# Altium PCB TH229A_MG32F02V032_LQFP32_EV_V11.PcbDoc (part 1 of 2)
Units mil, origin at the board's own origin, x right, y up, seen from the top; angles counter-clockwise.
Board outline 4094.49 x 2637.8 mil, 2 copper layers (Top Layer, Bottom Layer); 124 components, 101 nets, 554 pads, 263 vias.
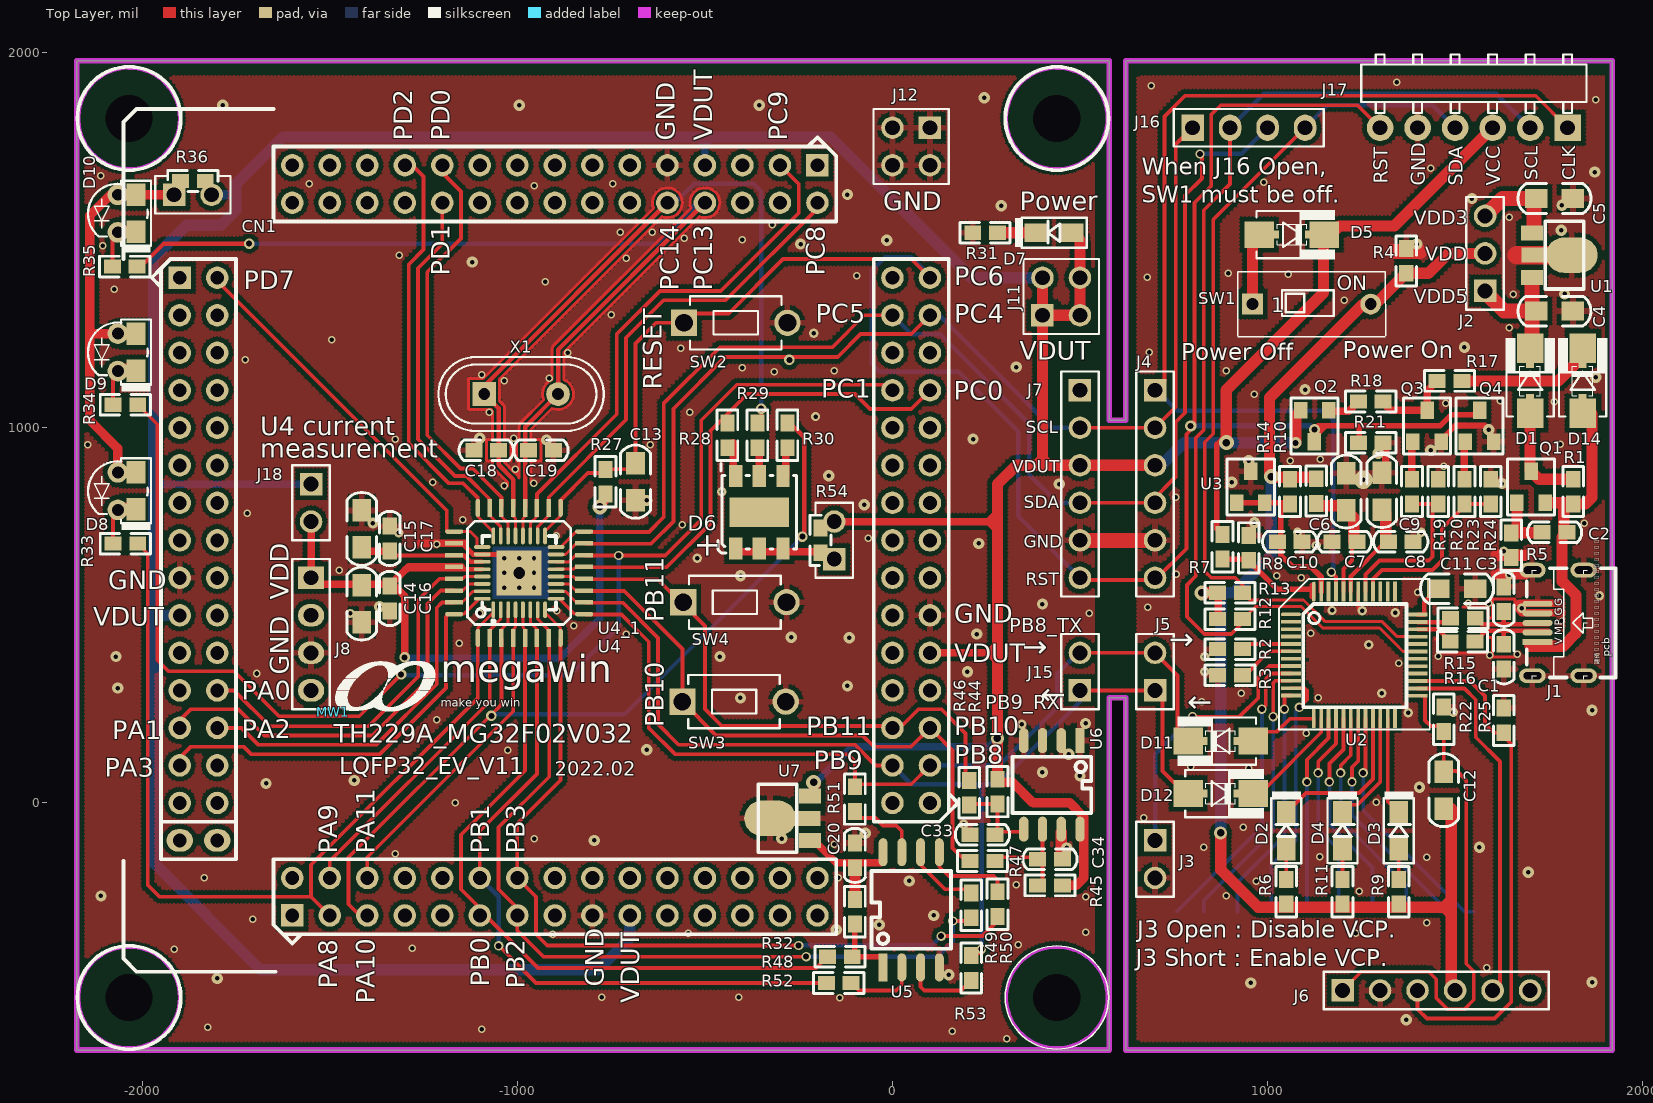
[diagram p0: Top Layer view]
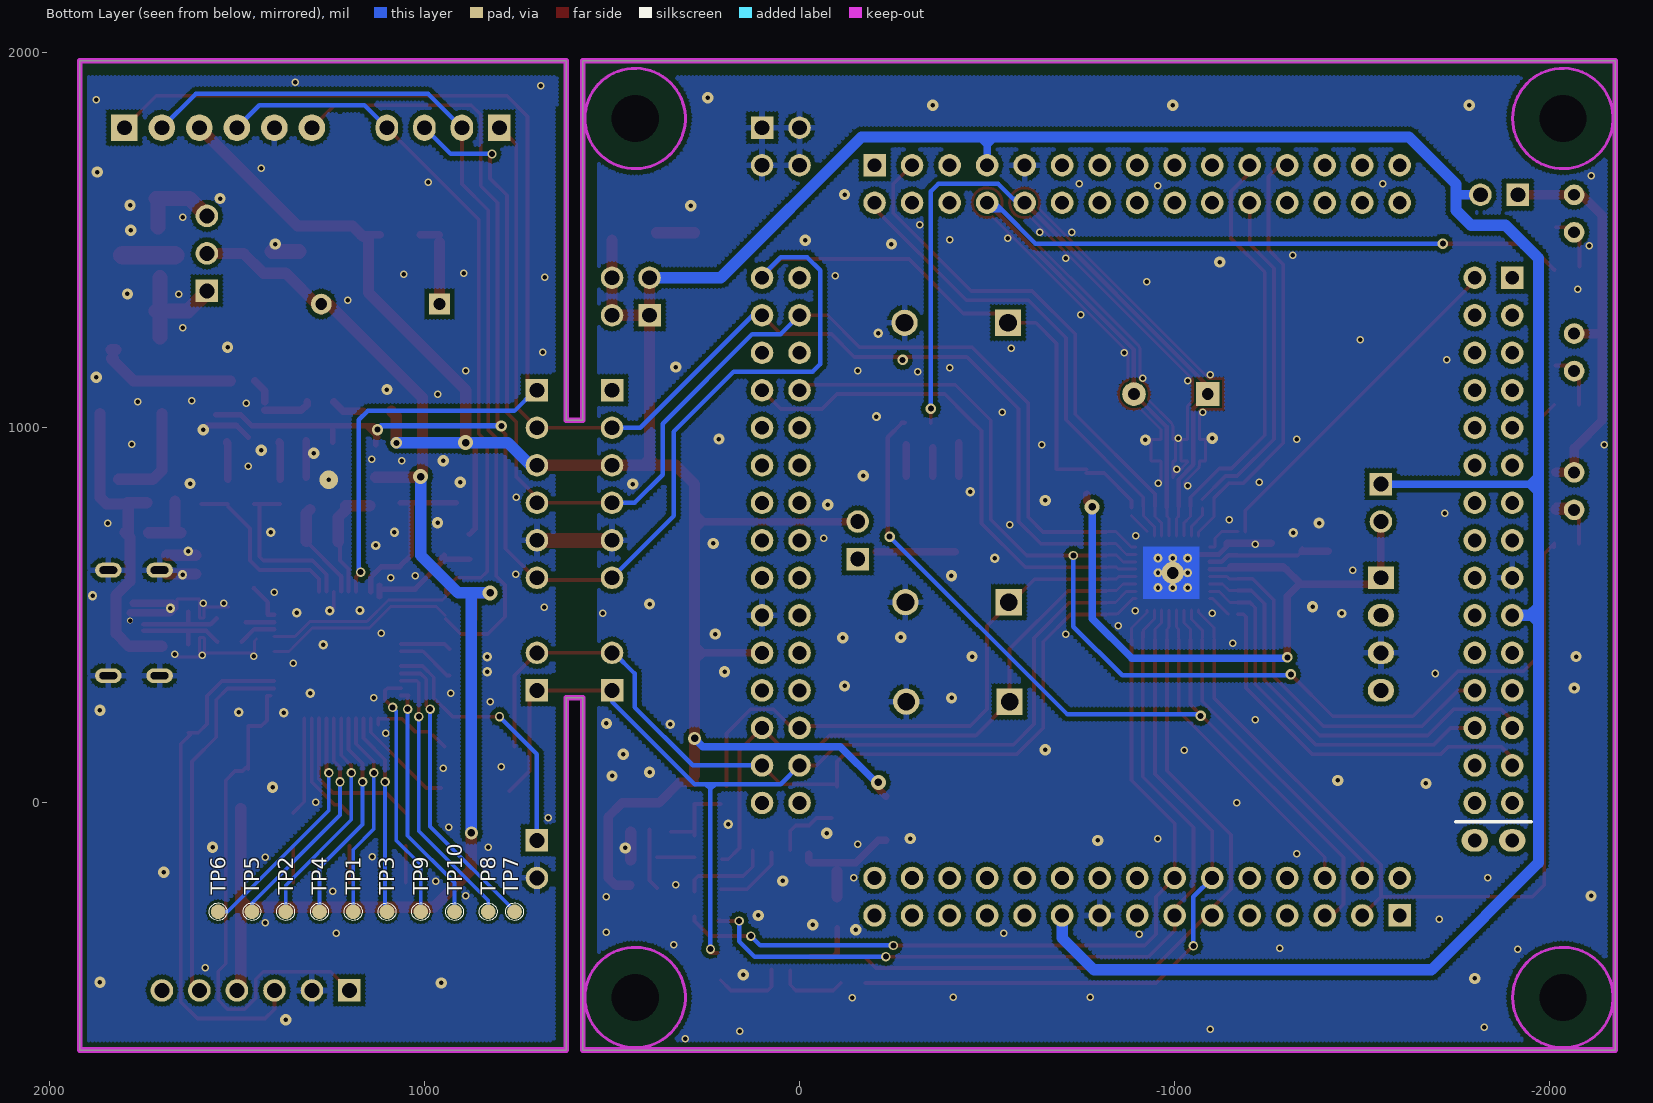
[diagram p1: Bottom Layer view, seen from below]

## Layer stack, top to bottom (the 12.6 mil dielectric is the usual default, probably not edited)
Top Layer: signal copper 1.4
Dielectric: dielectric 12.6, FR-4, Dk 4.8
Bottom Layer: signal copper 1.4

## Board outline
-2175.04,-658.74 -2175.04,1979.06 578.35,1979.06 578.35,1020 621.65,1020 621.65,1979.06 1919.45,1979.06 1919.45,-658.74 621.65,-658.74 621.65,280 578.35,280 578.35,-658.74

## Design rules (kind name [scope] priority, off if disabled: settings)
Clearance 12 [All] p1: gap=12
Clearance 7 [All] p2 off: gap=7
Clearance 6 [All] p3: gap=6
HoleSize 500-HoleSize [All] p1: absolutevalues=TRUE maxlimit=1500 minlimit=1 maxpercent=80.000 minpercent=20.000
PolygonConnect VIA [ISVIA] p1: connectstyle=Direct reliefconductorwidth=10 reliefentries=4 polygonreliefangle="90 Angle"
PolygonConnect "15 PolygonConnect" [All] p2: connectstyle=Relief reliefconductorwidth=15 reliefentries=4 polygonreliefangle="90 Angle"
RoomDefinition 2_MG32F02V032_V11 [InComponentClass('2_MG32F02V032_V11')] p1: confinementstyle=ConfineIn formatcopy=TRUE lockcomponents=FALSE outline -2365.04,-833.74 2065,-833.74 2065,2051.26 -2365.04,2051.26
RoomDefinition 1_MLink_V11 [InComponentClass('1_MLink_V11')] p2: confinementstyle=ConfineIn formatcopy=TRUE lockcomponents=FALSE outline -2285.04,-878.74 2004.96,-878.74 2004.96,2116.26 -2285.04,2116.26
RoutingVias [All] p1: holewidth=16 width=28 viastyle="Through Hole" minholewidth=16 minwidth=25 maxholewidth=28 maxwidth=50
ShortCircuit [All] p1 off: allowed=FALSE
SilkscreenOverComponentPads [All] p1: minsilkscreentomaskgap=10
SolderMaskExpansion [All] p1: expansion=4
UnRoutedNet [All] p1 off:
Width [All] p1: maxlimit=100 minlimit=6 preferedwidth=10
24 further rules are at their usual default settings.

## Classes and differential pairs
component class 2_MG32F02V032_V11: C13 C14 C15 C16 C17 C18 C19 C20 C33 C34 CN1 D6 D7 D8 D9 D10 J7 J8 J11 J12 J15 J18 R27 R28 R29 R30 R31 R32 R33 R34 R35 R36 R44 R45 R46 R47 R48 R49 R50 R51 R52 R53 R54 SW2 SW3 SW4 U4 U4_1 U5 U6 U7 X1
component class 1_MLink_V11: C1 C2 C3 C4 C5 C6 C7 C8 C9 C10 C11 C12 D1 D2 D3 D4 D5 D11 D12 D14 J1 J2 J3 J4 J5 J6 J16 J17 MW1 Q1 Q2 Q3 Q4 R1 R2 R3 R4 R5 R6 R7 R8 R9 R10 R11 R12 R13 R14 R15 R16 R17 R18 R19 R20 R21 R22 R23 R24 R25 SW1 TP1 TP2 TP3 TP4 TP5 TP6 TP7 TP8 TP9 TP10 U1 U2 U3

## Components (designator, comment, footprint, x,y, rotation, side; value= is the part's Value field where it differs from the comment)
C1 "15pF" 0603C 1630,390 r90 top
C2 "0.1uF" 0603C 1764.96,721.26 r0 top
C3 "15pF" 0603C 1630,543 r270 top
C4 "4.7uF" 0805C 1764.96,1311.26 r0 top
C5 "4.7uF" 0805C 1764.96,1611.26 r0 top
C6 "4.7uF" 0805C 1209.96,830 r90 top
C7 "0.1uF" 0603C 1205,696.26 r180 top
C8 "0.1uF" 0603C 1355,696.26 r0 top
C9 "4.7uF" 0805C 1304.96,831.26 r90 top
C10 "0.1uF" 0603C 1059.05,696.26 r180 top
C11 "4.7uF" 0805C 1504.96,571.26 r0 top
C12 "4.7uF" 0805C 1470,34 r90 top
C13 "4.7uF" 0805C -685.04,856.26 r90 top
C14 "4.7uF" 0805C -1415.04,531.26 r270 top
C15 "4.7uF" 0805C -1415.04,730.47 r90 top
C16 "0.1uF" 0603C -1340.1,545 r90 top
C17 "0.1uF" 0603C -1340.04,705 r270 top
C18 "NC" 0603C -1083,940 r0 top
C19 "NC" 0603C -937,940 r180 top
C20 "1uF" 0603C -100,-140 r270 top
C33 "47pF" 0603C 240,-85 r0 top
C34 "47pF" 0603C 420,-150 r180 top
CN1 "QFP122-CKT" QFP122-P2.54-CKT -900,700 r0 top locked
D1 "1N5817" DIODE_SMA_SOD323 1699.96,1125 r90 top
D2 "Yellow" 0805D 1050,-73.74 r90 top
D3 "Green" 0805D 1350,-73.74 r90 top
D4 "Red" 0805D 1200,-73.74 r90 top
D5 "1N5817" DIODE_SMA_SOD323 1064.96,1515 r0 top
D6 "GTG5050RGBC" LED6P_RGB_SMD_50X50 -355,775 r90 top
D7 "Yellow" 0805D 430.79,1520 r180 top
D8 "Red" LED38+0805 -2065.04,831.26 r270 top
D9 "Yellow" LED38+0805 -2065.04,1201.26 r270 top
D10 "Green" LED38+0805 -2065.04,1571.26 r270 top
D11 "1N5817" DIODE_SMA_SOD323 875,165 r180 top
D12 "1N5817" DIODE_SMA_SOD323 875,25 r0 top
D14 "1N5817" DIODE_SMA_SOD323 1839.96,1125 r90 top
J1 "MICRO_USB" USB_MICRO_7.X6P065 1842.76,479.85 r90 top
J2 "2&3 (0 ohm)" PS3P254 1580,1365 r90 top
J3 "VCP Option" PS2P254 700,-100 r270 top
J4 "OnBoard ICP/SWD Connector" PS6P254 700,1100 r270 top
J5 "NC" PS2P254 700,300 r90 top
J6 "CON6" PS6P254 1200,-500 r0 top
J7 "CON6" PS6P254 500,1100 r270 top
J8 "1&2 (0 ohm)" PS4P254 -1550,600 r270 top
J11 "CONN SOCKET 2x2/SM" PS2X2P254 400,1300 r0 top
J12 "CONN SOCKET 2x2/SM" PS2X2P254 100,1800 r180 top
J15 "NC" PS2P254 500,300 r90 top
J16 "When J16 Open, SW1 must be off." PS4P254 800,1800 r0 top
J17 "Off Board ICP/SWD Connector" PS6P254_90 1800,1800 r180 top locked
J18 "JUMPER" PS2P254 -1550,850 r270 top
MW1 "MW-A4" MEGAWIN_3.4 -1490.72,242.24 r0 top
Q1 "IRLML6402" SOT23 1702.5,841.97 r0 top
Q2 "2N3906" SOT23 1125.46,1005 r180 top
Q3 "3904" SOT23_132 1425,1005 r0 top
Q4 "3904" SOT23_132 1565,1005 r0 top
R1 "NC" 0603R#1 1815,830 r270 top
R2 "0" 0603R#1 900,410 r0 top
R3 "NC" 0603R#1 900,340 r0 top
R4 "3.3K" 0603R#1 1370,1445 r270 top
R5 "1M" 0603R#1 1650,687 r270 top
R6 "1K" 0603R#1 1050,-236.74 r270 top
R7 "30K" 0603R#1 880,683 r90 top
R8 "10K" 0603R#1 950,680 r270 top
R9 "1K" 0603R#1 1350,-236.74 r270 top
R10 "10" 0603R#1 1129.96,831.26 r90 top
R11 "1K" 0603R#1 1200,-236.74 r270 top
R12 "1.5K" 0603R#1 900,490 r180 top
R13 "1.5K" 0603R#1 900,560 r180 top
R14 "1K" 0603R#1 1059.96,830 r270 top
R15 "30" 0603R#1 1520.84,492.31 r180 top
R16 "30" 0603R#1 1520,430 r180 top
R17 "4.7K" 0603R#1 1484.96,1125 r0 top
R18 "1K" 0603R#1 1275,1070 r0 top
R19 "4.7K" 0603R#1 1385,830 r270 top
R20 "10K" 0603R#1 1455,830 r270 top
R21 "1M" 0603R#1 1275,960 r180 top
R22 "47K" 0603R#1 1470,223 r90 top
R23 "4.7K" 0603R#1 1525,830 r270 top
R24 "10K" 0603R#1 1595,830 r270 top
R25 "47K" 0603R#1 1630,220 r270 top
R27 "47K" 0603R#1 -765.04,856.26 r270 top
R28 "510" 0603R#1 -440,980 r90 top
R29 "510" 0603R#1 -360,980 r90 top
R30 "3K" 0603R#1 -280,980 r90 top
R31 "1K" 0603R#1 247,1520 r180 top
R32 "47K" 0603R#1 -100,-290 r270 top
R33 "510" 0603R#1 -2045.04,691.26 r0 top
R34 "510" 0603R#1 -2045.04,1061.26 r0 top
R35 "510" 0603R#1 -2046.48,1429.81 r0 top
R36 "0" PS2p254+0603 -1915.04,1621.26 r0 top
R44 "10K" 0603R#1 280,30 r90 top
R45 "10K" 0603R#1 420,-220 r0 top
R46 "NC" 0603R#2 204.96,27 r270 top
R47 "NC" 0603R#1 240,-155 r180 top
R48 "NC" 0603R#1 -140,-410 r180 top
R49 "NC" 0603R#1 210,-273 r270 top
R50 "NC" 0603R#1 280,-270 r270 top
R51 "NC" 0603R#1 -100,10 r90 top
R52 "NC" 0603R#1 -143,-480 r180 top
R53 "NC" 0603R#1 210,-440 r90 top
R54 "0" PS2p254+0603 -155.04,650 r90 top
SW1 "SW KEY-SPST" DIP2_SW 960.04,1330 r0 top
SW2 "SW TACT-SPST" SW_T_2P -417.8,1280 r0 top
SW3 "SW TACT-SPST" SW_T_2P -422.21,270 r0 top
SW4 "SW TACT-SPST" SW_T_2P -420,535 r0 top
TP1 "T POINT A" PIN1_1H0 1190,-290 r90 bottom
TP2 "T POINT A" PIN1_1H0 1370,-290 r90 bottom
TP3 "T POINT A" PIN1_1H0 1100,-290 r180 bottom
TP4 "T POINT A" PIN1_1H0 1280,-290 r180 bottom
TP5 "T POINT A" PIN1_1H0 1460,-290 r180 bottom
TP6 "T POINT A" PIN1_1H0 1550,-290 r180 bottom
TP7 "T POINT A" PIN1_1H0 760,-290 r180 bottom
TP8 "T POINT A" PIN1_1H0 830,-290 r180 bottom
TP9 "T POINT A" PIN1_1H0 1010,-290 r180 bottom
TP10 "T POINT A" PIN1_1H0 920,-290 r90 bottom
U1 "AIC1734-33(SOT-89)" SOT89 1704.96,1460.31 r270 top
U2 "MG84FG516_LQFP48" LQFP48_7X7_050 1231.47,394.39 r270 top locked
U3 "TL431A" SOT23 954.96,841.97 r0 top
U4 "MG32F02A_LQFP48" QFP32-P0.8-Z8.8X8.8 -995.04,613.32 r90 top locked
U4_1 "MG32F02A__QFN32" QFN32-P0.5-Z5X5-TPAD -995.04,613.32 r90 top locked
U5 "MX25LXX-SOP" SO8_208P127 50,-285 r0 top
U6 "24C16-SOP" SO8_150P127 500,166.22 r270 top
U7 "AIC1734-33(SOT-89)" SOT89 -220,-40.94 r90 top
X1 "NC" X49U -990,1090 r0 top locked

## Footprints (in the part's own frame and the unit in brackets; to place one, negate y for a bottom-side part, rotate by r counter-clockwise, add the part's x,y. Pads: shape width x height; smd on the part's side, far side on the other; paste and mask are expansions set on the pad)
0603C [mil]
  rect 45x38 smd: 1(33,0) 2(-33,0)
  silkscreen extent -72,-28 72,28
0603R#1 [mil]
  rect 45x38 smd: 1(33,0) 2(-33,0)
  silkscreen extent -67,-28 67,28
0603R#2 [mil]
  rect 45x38 smd: 1(-33,0) 2(33,0)
  silkscreen extent -67,-28 67,28
0805C [mil]
  rect 60x50 smd: 1(-49.21,0) 2(49.21,0)
  silkscreen extent -97,-39 97,39
0805D [mil]
  rect 60x50 smd: 1(-49.21,0) 2(49.21,0)
  silkscreen extent -87,-40 104,40
DIODE_SMA_SOD323 [mm]
  rect 2x1.8 smd: 1(-2.2,0) 2(2.2,0)
  rect 0.95x0.54 smd: 1(-1.35,0) 2(1.35,0)
  silkscreen extent -2.4,-1.68 2.92,1.68
DIP2_SW [mm]
  rect 1.4x1.4 hole 0.8: 1(0,0)
  round 1.4 hole 0.8: 2(8,0)
  silkscreen extent -1.02,-2.2 9.02,2.2
LED6P_RGB_SMD_50X50 [mm]
  rect 2x4 smd: 0(0,0)
  rect 1.5x0.9 smd: 1(-2.45,1.6) 2(2.45,1.6) 3(-2.45,0) 4(2.45,0) 5(-2.45,-1.6) 6(2.45,-1.6)
  silkscreen extent -2.76,-2.52 3.3,2.79
LED38+0805 [mm]
  round 1.4 hole 0.8: 1(-1.27,0) 2(1.27,0)
  rect 1.524x1.27 smd: 1(-1.267,1.237) 2(1.233,1.237)
  silkscreen extent -2.23,-2.02 2.64,2.25
LQFP48_7X7_050 [mm]
  oval 0.254x1.35 smd: 1(-2.75,-4.292)
  rect 0.254x1.35 smd: 2(-2.25,-4.292) 3(-1.75,-4.292) 4(-1.25,-4.292) 5(-0.75,-4.292) 6(-0.25,-4.292) 7(0.25,-4.292) 8(0.75,-4.292) 9(1.25,-4.292) 10(1.75,-4.292) 11(2.25,-4.292) 12(2.75,-4.292) 25(2.763,4.292) 26(2.263,4.292) 27(1.763,4.292) 28(1.263,4.292) 29(0.763,4.292) 30(0.263,4.292) 31(-0.237,4.292) 32(-0.737,4.292) 33(-1.237,4.292) 34(-1.737,4.292) 35(-2.237,4.292) 36(-2.737,4.292)
  rect 1.35x0.254 smd: 13(4.286,-2.744) 14(4.286,-2.244) 15(4.286,-1.744) 16(4.286,-1.244) 17(4.286,-0.744) 18(4.286,-0.244) 19(4.286,0.256) 20(4.286,0.756) 21(4.286,1.256) 22(4.286,1.756) 23(4.286,2.256) 24(4.286,2.756) 37(-4.286,2.756) 38(-4.286,2.256) 39(-4.286,1.756) 40(-4.286,1.256) 41(-4.286,0.756) 42(-4.286,0.256) 43(-4.286,-0.244) 44(-4.286,-0.744) 45(-4.286,-1.244) 46(-4.286,-1.744) 47(-4.286,-2.244)
  oval 1.35x0.254 smd: 48(-4.286,-2.744)
  silkscreen extent -5.15,-5.09 5.05,5.11
MEGAWIN_3.4 [mil]
  silkscreen extent 5,3 272,136
PIN1_1H0 [mm]
  round 1 smd: 1(0,0)
  silkscreen extent -0.6,-0.6 0.6,0.6
PS2P254 [mil]
  rect 60x60 hole 39.37: 1(0,0)
  round 60 hole 39.37: 2(100,0)
  silkscreen extent -50,-50 150,50
PS2p254+0603 [mil]
  rect 60x60 hole 39.37: 1(0,0)
  rect 45x38 smd: 1(17,36.85) 2(83,36.85)
  round 60 hole 39.37: 2(100,0)
  silkscreen extent -50,-50 150,64
PS2X2P254 [mil]
  rect 60x60 hole 39.37: 1(0,0)
  round 60 hole 39.37: 2(0,100) 3(100,0) 4(100,100)
  silkscreen extent -50,-50 150,150
PS3P254 [mil]
  rect 60x60 hole 39.37: 1(0,0)
  round 60 hole 39.37: 2(100,0) 3(200,0)
  silkscreen extent -50,-50 250,50
PS4P254 [mil]
  rect 60x70 hole 39.37: 1(0,0)
  oval 60x70 hole 39.37: 2(100,0) 3(200,0) 4(300,0)
  silkscreen extent -50,-50 350,50
PS6P254 [mil]
  rect 60x60 hole 39.37: 1(0,0)
  round 60 hole 39.37: 2(100,0) 3(200,0) 4(300,0) 5(400,0) 6(500,0)
  silkscreen extent -50,-50 550,50
PS6P254_90 [mm]
  rect 1.8x1.8 hole 1: 1(0,0)
  round 1.8 hole 1: 2(2.54,0) 3(5.08,0) 4(7.62,0) 5(10.16,0) 6(12.7,0)
  silkscreen extent -1.27,-4.95 13.97,-1
QFN32-P0.5-Z5X5-TPAD [mm]
  oval 1.143x0.254 smd: 1(-2.5,1.75) 2(-2.5,1.25) 3(-2.5,0.75) 4(-2.5,0.25) 5(-2.5,-0.25) 6(-2.5,-0.75) 7(-2.5,-1.25) 8(-2.5,-1.75) 17(2.5,-1.75) 18(2.5,-1.25) 19(2.5,-0.75) 20(2.5,-0.25) 21(2.5,0.25) 22(2.5,0.75) 23(2.5,1.25) 24(2.5,1.75)
  oval 0.254x1.143 smd: 9(-1.75,-2.5) 10(-1.25,-2.5) 11(-0.75,-2.5) 12(-0.25,-2.5) 13(0.25,-2.5) 14(0.75,-2.5) 15(1.25,-2.5) 16(1.75,-2.5) 25(1.75,2.5) 26(1.25,2.5) 27(0.75,2.5) 28(0.25,2.5) 29(-0.25,2.5) 30(-0.75,2.5) 31(-1.25,2.5) 32(-1.75,2.5)
  rect 3.048x3.048 smd: 33(0,0)
  round 1.5 hole 0.8: 34(0,0)
  round 0.6 hole 0.3: 35(0,1) 36(1,1) 37(1,0) 38(1,-1) 39(0,-1) 40(-1,-1) 41(-1,0) 42(-1,1)
  silkscreen extent -3.35,-2.5 2.5,2.5
QFP32-P0.8-Z8.8X8.8 [mil]
  oval 48x12 smd: 1(-173.23,110.24) 8(-173.23,-110.24) 17(173.23,-110.24) 24(173.23,110.24)
  rect 48x12 smd: 2(-173.23,78.74) 3(-173.23,47.24) 4(-173.23,15.75) 5(-173.23,-15.75) 6(-173.23,-47.24) 7(-173.23,-78.74) 18(173.23,-78.74) 19(173.23,-47.24) 20(173.23,-15.75) 21(173.23,15.75) 22(173.23,47.24) 23(173.23,78.74)
  oval 12x48 smd: 9(-110.24,-173.23) 16(110.24,-173.23) 25(110.24,173.23) 32(-110.24,173.23)
  rect 12x48 smd: 10(-78.74,-173.23) 11(-47.24,-173.23) 12(-15.75,-173.23) 13(15.75,-173.23) 14(47.24,-173.23) 15(78.74,-173.23) 26(78.74,173.23) 27(47.24,173.23) 28(15.75,173.23) 29(-15.75,173.23) 30(-47.24,173.23) 31(-78.74,173.23)
  silkscreen extent -138,-138 138,138
QFP122-P2.54-CKT [mil]
  rect 60x60 hole 37: 1(-700,-1000) 61(700,1000) 91(-1000,700)
  round 60 hole 37: 2(-700,-900) 3(-600,-1000) 4(-600,-900) 5(-500,-1000) 6(-500,-900) 7(-400,-1000) 8(-400,-900) 9(-300,-1000) 10(-300,-900) 11(-200,-1000) 12(-200,-900) 13(-100,-1000) 14(-100,-900) 15(0,-1000) 16(0,-900) 17(100,-1000) 18(100,-900) 19(200,-1000) 20(200,-900) 21(300,-1000) 22(300,-900) 23(400,-1000) 24(400,-900) 25(500,-1000) 26(500,-900) 27(600,-1000) 28(600,-900) 29(700,-1000) 30(700,-900) 31(1000,-700) 32(900,-700) 33(1000,-600) 34(900,-600) 35(1000,-500) 36(900,-500) 37(1000,-400) 38(900,-400) 39(1000,-300) 40(900,-300) 41(1000,-200) 42(900,-200) 43(1000,-100) 44(900,-100) 45(1000,0) 46(900,0) 47(1000,100) 48(900,100) 49(1000,200) 50(900,200) 51(1000,300) 52(900,300) 53(1000,400) 54(900,400) 55(1000,500) 56(900,500) 57(1000,600) 58(900,600) 59(1000,700) 60(900,700) 62(700,900) 63(600,1000) 64(600,900) 65(500,1000) 66(500,900) 67(400,1000) 68(400,900) 69(300,1000) 70(300,900) 71(200,1000) 72(200,900) 73(100,1000) 74(100,900) 75(0,1000) 76(0,900) 77(-100,1000) 78(-100,900) 79(-200,1000) 80(-200,900) 81(-300,1000) 82(-300,900) 83(-400,1000) 84(-400,900) 85(-500,1000) 86(-500,900) 87(-600,1000) 88(-600,900) 89(-700,1000) 90(-700,900) 92(-900,700) 93(-1000,600) 94(-900,600) 95(-1000,500) 96(-900,500) 97(-1000,400) 98(-900,400) 99(-1000,300) 100(-900,300) 101(-1000,200) 102(-900,200) 103(-1000,100) 104(-900,100) 105(-1000,0) 106(-900,0) 107(-1000,-100) 108(-900,-100) 109(-1000,-200) 110(-900,-200) 111(-1000,-300) 112(-900,-300) 113(-1000,-400) 114(-900,-400) 115(-1000,-500) 116(-900,-500) 117(-1000,-600) 118(-900,-600) 119(-1000,-700) 120(-900,-700)
  oval 70x60 hole 37: 121(-1000,-800) 122(-900,-800)
  silkscreen extent -1150,-1150 1075,1150
SO8_150P127 [mil]
  rect 67x25 smd: 1(0,0)
  oval 67x25 smd: 2(0,-50) 3(0,-100) 4(0,-150) 5(236.22,-150) 6(236.22,-100) 7(236.22,-50) 8(236.22,0)
  silkscreen extent 43,-180 193,30
SO8_208P127 [mm]
  rect 0.6x1.9 smd: 1(-1.905,-3.9)
  oval 0.6x1.9 smd: 2(-0.635,-3.9) 3(0.635,-3.9) 4(1.905,-3.9) 5(1.905,3.9) 6(0.635,3.9) 7(-0.635,3.9) 8(-1.905,3.9)
  silkscreen extent -2.69,-2.63 2.69,2.63
SOT23 [mil]
  rect 36x43.31 smd: 1(-37.5,-41.97) 2(37.5,-41.97)
  rect 36x46.06 smd: 3(0.5,41.97)
  silkscreen extent -63,-74 63,75
SOT23_132 [mil]
  rect 36x43.31 smd: 1(-37.5,-41.97) 3(37.5,-41.97)
  rect 36x46.06 smd: 2(0.5,41.97)
  silkscreen extent -63,-74 63,75
SOT89 [mm]
  rect 1.016x1.5 smd: 1(-1.5,0) 3(1.5,0)
  oval 2.4x3.5 smd: 2(0,2.7)
  rect 1.016x2.6 smd: 2(0,0.6)
  silkscreen extent -2.3,0.9 2.3,3.5
SW_T_2P [mil]
  rect 70x70 hole 47.24: 1(-137.79,0)
  round 70 hole 47.24: 2(137.8,0)
  silkscreen extent -122,-71 122,71
USB_MICRO_7.X6P065 [mm] "J?"
  rect 0.4x2.032 smd: 1(-1.3,3.119)
  oval 0.4x2.032 smd: 2(-0.65,3.119) 3(0,3.119) 4(0.65,3.119) 5(1.3,3.119)
  oval 1x1.8 hole 0.5 slot 1.2 at 90 deg: 6(3.575,3.47) 7(3.575,0) 8(-3.575,0) 9(-3.575,3.47)
  silkscreen extent -3.83,-2.15 3.7,3.85
X49U [mm]
  rect 1.6x1.6 hole 0.8: 1(-2.5,0)
  round 1.6 hole 0.8: 2(2.5,0)
  silkscreen extent -5.6,-2.5 5.6,2.5

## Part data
C1 C3 C7 C12 C13 C14 C15 C16 C17: library part "CAP NP_Dup1"
C2 C8 C10: library part "CAP NP"
C4 C5: library part "C NP"
C6 C9 C11: library part CAP
C18 C19: library part "C NP_Dup1"
C20 C33 C34: library part CAP-NP
D1 D5 D11 D12 D14: library part "DIODE SCHOTTKY"
D2 D3 D4: library part Led0_0
D6: library part LED_GTG5050RGBC
D7 D8 D9 D10: library part LED
J1: library part USB_Micro
J2: library part CON3
J3 J5 J15: library part CON2
J4 J17: library part CON6
J7: library part CON6_Dup1
J8 J16: library part CON4
MW1: library part MW_A4_2
Q1: library part "MOSFET P GSD"
Q2: library part 2N3906_0
Q3 Q4: library part "NPN BCE"
R1 R2 R3 R4 R27: library part R_Dup4
R5 R6 R7 R8 R9 R11 R12 R13 R17 R18 R19 R22 R23 R25: library part R_Dup2
R10 R14 R15 R16 R28 R29 R30 R31 R32 R33 R34 R35 R36 R46 R47 R48 R49 R50 R51 R52 R53 R54: library part R_Dup5
R20 R21 R24: library part R_Dup1
R44 R45: library part R
U1 U7: library part AIC1722-33
U3: library part TL431/CYL
U4: library part IC32_MG32F02V032
U4_1: library part IC-MG32F02V032-QFN32_0
U5: library part ICM-25LXX
U6: library part ICM-24CXX
X1: library part CRYSTAL

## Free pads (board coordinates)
  round 120 hole 125.98 unplated: 0(-2035.04,-518.74) 0(-2035.04,1824.68) 0(438.35,-518.74) 0(438.35,1824.68)

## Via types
v1: diameter 20, hole 12, Top Layer to Bottom Layer, tented both sides, 128 vias
v2: diameter 30, hole 12, Top Layer to Bottom Layer, tented both sides, 72 vias
v3: diameter 25, hole 12, Top Layer to Bottom Layer, tented both sides, 24 vias
v4: diameter 25, hole 16, Top Layer to Bottom Layer, tented both sides, 20 vias
v5: diameter 28, hole 16, Top Layer to Bottom Layer, 7 vias
v6: diameter 40, hole 20, Top Layer to Bottom Layer, tented both sides, 5 vias
v7: diameter 30, hole 16, Top Layer to Bottom Layer, tented both sides, 3 vias
v8: diameter 35, hole 20, Top Layer to Bottom Layer, tented both sides, 2 vias
v9: diameter 15, hole 12, Top Layer to Bottom Layer, tented both sides, 1 vias
v10: diameter 50, hole 12, Top Layer to Bottom Layer, tented both sides, 1 vias

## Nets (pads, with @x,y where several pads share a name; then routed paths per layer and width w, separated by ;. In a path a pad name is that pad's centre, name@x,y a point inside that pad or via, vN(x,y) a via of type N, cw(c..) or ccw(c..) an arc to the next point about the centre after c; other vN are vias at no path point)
2.495V: C10.1 R14.1 U2.47 U3.1 U3.2 | length 455.3
  Top Layer w15: U3.1@914.96,800 U3.1@917.46,800 U3.2@992.46,800 1034.96,800 1034.96,797 1034.96,696.26 1034.96,661.26 1066.22,630 1115,630 1143.14,601.86 U2.47@1143.14,563.13 ; 1039.96,800 1059.96,800 R14.1@1064.96,800
516P24: TP7.1 U2.9 | length 790.4
  Top Layer w10: v4(985,250) 995,260 995,330 1010.18,345.18 U2.9@1062.48,345.18
  Bottom Layer w10: TP7.1@758.86,-288.86 985,-62.72 v4(985,250)
516P25: TP8.1 U2.10 | length 736.4
  Top Layer w10: v4(1015,230) 1015,320 1020.49,325.49 U2.10@1062.48,325.49
  Bottom Layer w10: TP8.1@830,-290 830,-260.15 1015,-75.15 v4(1015,230)
516P26: TP9.1 U2.11 | length 674.3
  Top Layer w10: U2.11@1062.48,305.81 1099.19,305.81 1105,300 1105,275 v4(1085,255)
  Bottom Layer w10: TP9.1@1010,-290 1010,-165 1075,-100 1075,245 v4(1085,255)
516P27: TP10.1 U2.12 | length 649.5
  Top Layer w10: v4(1045,250) 1045,283.23 1042.11,286.12 U2.12@1062.48,286.12
  Bottom Layer w10: TP10.1@920,-290 920,-212.57 1045,-87.57 v4(1045,250)
516P32: TP3.1 U2.15 | length 762.5
  Top Layer w10: v4@1105,55 v4(1105,56.26) 1105,115 1162.82,172.82 U2.15@1162.82,225.65
  Bottom Layer w10: TP3.1@1105,-285 1105,-30 ; 1105,-257.87 1105,-30 ; v4@1105,55 1105,-30
516P33: TP1.1 U2.16 | length 558.1
  Top Layer w10: v4(1135,80) 1135,110 1182.51,157.51 U2.16@1182.51,225.65
  Bottom Layer w10: v4(1135,80) 1135,-69.85 1190,-124.85 TP1.1@1190,-290
516P34: TP4.1 U2.17 | length 578.7
  Top Layer w10: v4@1165,55 v4(1165,56.26) 1165,105 1202.19,142.19 U2.17@1202.19,225.65
  Bottom Layer w10: v4@1165,55 1165,-57.43 1280,-172.43 TP4.1@1280,-290
516P35: TP2.1 U2.18 | length 599.3
  Top Layer w10: v4(1195,80) 1195,100 1221.88,126.88 U2.18@1221.88,225.65
  Bottom Layer w10: v4(1195,80) 1195,-45 1370,-220 TP2.1@1370,-290
516P36: TP5.1 U2.19 | length 619.9
  Top Layer w10: v4@1225,55 v4(1225,56.26) 1225,95 1241.56,111.56 U2.19@1241.56,225.65
  Bottom Layer w10: v4@1225,55 1225,-32.57 1460,-267.57 TP5.1@1460,-290
516P37: TP6.1 U2.20 | length 655.2
  Top Layer w10: v4(1255,80) 1261.25,86.25 U2.20@1261.25,225.65
  Bottom Layer w10: v4(1255,80) 1255,-20.15 1524.85,-290 TP6.1@1550,-290
CHIP_VDD: C14.1 C16.1 J8.1 J18.2 R27.1 U4.28 U4_1.28 | length 1870.3
  Top Layer w11: U4.28@-1168.27,626.26 U4.28@-1160.04,626.26
  Top Layer w12: -1300,623.17 -1296.83,623.17 -1168.27,623.17 U4_1.28@-1093.47,623.17
  Top Layer w20: J8.1@-1550,600 J18.2@-1550,750 ; J8.1@-1533,583 -1415.04,583 -1340.1,583 -1337,583 -1296.83,623.17 -1290,630 -1168.27,630 U4.28@-1150,630 ; C16.1@-1326.78,578 -1300.04,551.26 v5@-1300.04,388.26 ; v6(-780.04,789.33) -765.04,804.33 R27.1@-765.04,823.26
  Bottom Layer w20: v5@-1300.59,386.26 -885.04,386.26 -780.04,491.26 v6(-780.04,789.33)
  other v5: -1300.59,388.26
D+: C3.1 J1.3 R15.2 | length 231.2
  Top Layer w12: R15.2@1553.84,492.31 1569.67,476.47 1719.96,476.47 J1.3@1750,476.47 ; 1630,481.47 C3.1@1630,510
D-: C1.1 J1.2 R16.2 | length 239.3
  Top Layer w12: R16.2@1553,430 1581.47,458.47 1719.96,458.47 J1.2@1750,458.47 ; C1.1@1630,423 1630,453.47
DET_VDUT: R7.2 R8.1 U2.48 | length 318.6
  Top Layer w15: R7.2@880,650 950,650 R8.1@957.56,650 ; R8.1@947.56,660 R8.1@955.28,652.28 ; R8.1@947.76,647.24 949,646 1025,570 1115.94,570 ; U2.48@1120,550 1120,563.13 U2.48@1120,580
DUT_CLK: J4.1 J17.1 U2.45 | length 2846.4
  Top Layer w10: J4.1@700,1100 725,1125 725,1830 780,1885 1715,1885 J17.1@1800,1800 ; v4(1169.88,615) 1182.51,602.37 U2.45@1182.51,563.13
  Bottom Layer w12: J4.1@700,1100 705,1100 760,1045 1151.22,1045 1174.96,1021.26 1174.96,620.08 v4(1169.88,615)
DUT_RST: C13.2 CN1.59 J4.6 J7.6 J17.6 Q2.3 Q4.2 R21.1 R27.2 SW2.1 U4.17 U4_1.17 | length 5808.4
  Top Layer w8: U4_1.17@-926.14,724.22 U4.17@-884.8,765.56
  Top Layer w10: U4.17@-884.8,786.55 -884.8,806.5 -812.04,879.26 R27.2@-765.04,879.26 ; R27.2@-765.04,889.26 C13.2@-685.04,889.26 ; C13.2@-685,889.26 C13.2@-685.04,905.47 -685,1225 -630,1280 SW2.1@-555.59,1280 ; SW2.1@-544.09,1305 -436.5,1305 -291.5,1450 50,1450 CN1.59@100,1400 ; J7.6@501,594 700,594 703,597 783.75,677.75 783.75,982.75 800.5,999.5 805,1004 805,1005 805,1600 850,1645 850,1835 875,1860 1240,1860 J17.6@1300,1800
  Top Layer w15: Q2.3@1124.96,975 Q2.3@1129.96,980 ; v7(1124.96,995) 1134.96,1005 1154.96,1005 ; Q2.3@1129.96,955 1129.96,963.03 Q2.3@1129.96,980 ; v7@1129.96,998 1129.96,995 Q2.3@1129.96,980 ; R21.1@1244.96,962 1244.96,1005 ; Q4.2@1555.59,1035 1489.96,1035 1459.96,1005 1244.96,1005 ; Q2.3@1129.96,980 1134.96,985 1154.96,1005 ; 1154.96,1005 1244.96,1005
  Bottom Layer w12: CN1.59@100,1400 CN1.59@105,1400 ; CN1.59@120,1400 CN1.59@105,1400 ; J7.6@500,600 335,765 335,990 175,1150 -35,1150 -55,1170 -55,1420 -20,1455 50,1455 102.5,1402.5 CN1.59@105,1400
  Bottom Layer w15: v7(795,1005) 1114.96,1005 v7(1124.96,995)
FAIL: D4.2 U2.22 | length 305.7
  Top Layer w10: D4.2@1200,-29 1202.24,-26.76 1224,-5 1240,-5 1300.62,55.62 U2.22@1300.62,225.65
FLASH_CEN: R32.1 R48.2 U5.1 | length 141.1
  Top Layer w15: R32.1@-100,-333 -100,-400 -98.5,-401.5 -90,-410 U5.1@-30,-410
FLASH_D0: R50.2 U5.5 | length 245
  Top Layer w10: U5.5@125,-126.46 U5.5@125,-131.46 125,-170 150,-195 270,-195 280,-205 R50.2@280,-237
FLASH_D1: R52.2 U5.2 | length 188
  Top Layer w10: R52.2@-110,-480 -90,-500 10,-500 25,-485 U5.2@25,-446.54
FLASH_D2: R53.2 U5.3 | length 196.8
  Top Layer w10: U5.3@75,-443.54 75,-490 85,-500 183,-500 R53.2@210,-473
FLASH_D3: R51.2 U5.7 | length 176
  Top Layer w10: R51.2@-85,-40 -45,-40 -25,-60 10,-60 25,-75 U5.7@25,-126.46
FLASH_SCK: R49.2 U5.6 | length 195.5
  Top Layer w10: U5.6@75,-131.46 75,-165 140,-230 R49.2@210,-230
I2C_SCL: C34.1 R45.2 R47.2 U6.6 | length 265.3
  Top Layer w10: R47.2@280,-145 C34.1@380,-145 ; R45.2@380,-227 R45.2@387,-220 400,-207 400,-150 U6.6@400,-70
I2C_SDA: C33.1 R44.2 R46.2 U6.5 | length 217
  Top Layer w10: R46.2@210,-3 R44.2@280,-3 C33.1@280,-77 ; C33.1@280,-87 280,-85 C33.1@280,-77 ; U6.5@343,-77 C33.1@280,-77
ICP/SWD_SCL: J16.2 J17.2 R12.2 U2.31 | length 2959.9
  Top Layer w8: R12.2@945,500 969,524 1088.96,524 1146.96,466 1298.96,466 1338.86,426.1 ; 1338.9,426.1 1361.27,403.73 U2.31@1400.46,403.73
  Top Layer w10: J16.2@900,1825 J16.2@900,1800 900,1650 830,1580 830,994 808.75,972.75 808.75,605.05 784.96,581.26 784.96,496.26 831.22,450 903,450 938,485 R12.2@943,490
  Bottom Layer w12: J16.2@900,1800 990,1890 1610,1890 J17.2@1700,1800
ICP/SWD_SDA: J16.4 J17.4 R13.2 U2.33 | length 2399.4
  Top Layer w8: R13.2@933,560 952,541 1096,541 1154,483 1306,483 1345.9,443.1 U2.33@1400.46,443.1
  Top Layer w10: R13.2@943,560 943,571 914,600 850,600 832.75,617.25 832.75,961.75 855,984 855,1555 J16.4@1100,1800
  Bottom Layer w12: J16.4@1100,1800 1160,1860 1440,1860 J17.4@1500,1800
MG_PA0: CN1.114 U4.29 U4_1.29 | length 1031.1
  Top Layer w8: U4.29@-1168.27,597.57 -1145.79,597.57 -1139.88,603.48 U4_1.29@-1093.47,603.48
  Top Layer w10: CN1.114@-1800,300 -1755,300 -1659.25,204.25 -1397.05,204.25 -1264.29,337.01 -1264.29,541.01 -1207.72,597.57 U4.29@-1168.27,597.57
MG_PA1: CN1.115 U4.30 U4_1.30 | length 1163.4
  Top Layer w8: U4.30@-1168.27,566.08 -1145.28,566.08 -1127.57,583.8 U4_1.30@-1093.47,583.8
  Top Layer w10: CN1.115@-1920,200 -1910,210 -1870,250 -1745,250 -1674.5,179.5 -1386.8,179.5 -1239.54,326.76 -1239.54,530.76 -1204.22,566.08 U4.30@-1168.27,566.08
MG_PA2: CN1.116 U4.31 U4_1.31 | length 1014.3
  Top Layer w8: U4.31@-1168.27,534.58 -1147.78,534.58 -1118.25,564.11 U4_1.31@-1093.47,564.11
  Top Layer w10: CN1.116@-1800,200 -1735,200 -1689.75,154.75 -1376.55,154.75 -1214.79,316.51 -1214.79,520.51 -1200.72,534.58 U4.31@-1168.27,534.58
MG_PA3: CN1.117 U4.32 U4_1.32 | length 1113.4
  Top Layer w8: -1143.21,503.09 -1101.87,544.43 U4_1.32@-1093.47,544.43
  Top Layer w10: CN1.117@-1920,100 -1910,110 -1870,150 -1730,150 -1710,130 -1366.3,130 -1190.04,306.26 -1190.04,496.26 -1183.21,503.09 U4.32@-1168.27,503.09
MG_PA8: CN1.3 R33.1 U4.1 U4_1.1 | length 2413.2
  Top Layer w8: U4.1@-1105.28,440.09 -1105.28,466.02 -1063.94,507.36 U4_1.1@-1063.94,514.9
  Top Layer w10: R33.1@-2010,681.26 -2012.04,681.26 R33.1@-2012.04,691.26 -1985.1,664.32 -1985.1,-218.68 -1953.78,-250 -1550,-250 ; CN1.3@-1500,-300 -1550,-250 ; U4.1@-1105.28,435.09 -1105.28,279.72 -1550,-165 -1550,-250
MG_PA9: CN1.4 U4.2 U4_1.2 | length 898.7
  Top Layer w8: U4.2@-1073.78,440.09 -1073.78,460.58 -1044.25,490.11 U4_1.2@-1044.25,514.9
  Top Layer w10: CN1.4@-1500,-200 -1500,-155 -1073.78,271.22 U4.2@-1073.78,435.09
MG_PA10: CN1.5 R30.1 U4.3 U4_1.3 | length 2380.2
  Top Layer w8: U4.3@-1042.28,440.09 -1042.28,463.08 -1024.57,480.8 U4_1.3@-1024.57,514.9
  Top Layer w10: CN1.5@-1400,-320 -1410,-310 -1450,-270 -1450,-145 -1071.09,233.91 -1042.28,262.72 U4.3@-1042.28,435.09
  Top Layer w12: R30.1@-280,1013 -273,1013 -235,975 -235,717.5 -240,712.5 v5(-240,710)
  Bottom Layer w12: v5@-1069.18,235.82 -714.18,235.82 v5(-240,710)
  other v5: -1069.18,232
MG_PA11: CN1.6 U4.4 U4_1.4 | length 873.6
  Top Layer w8: U4.4@-1010.79,440.09 -1010.79,462.57 -1004.88,468.48 U4_1.4@-1004.88,514.9
  Top Layer w10: CN1.6@-1400,-200 -1400,-145 -1010.79,244.21 U4.4@-1010.79,435.09
MG_PB0: CN1.11 R48.1 U4.5 U4_1.5 | length 1894.5
  Top Layer w8: U4_1.5@-985.2,514.9 -985.2,468.48 -979.29,462.57 U4.5@-979.29,440.09
  Top Layer w10: CN1.11@-1095,-290 -1092.5,-292.5 -945,-440 -203,-440 R48.1@-173,-410 ; CN1.11@-1090,-290 -1150,-230 -1150,-85 -979.29,85.71 U4.5@-979.29,435.09
MG_PB1: CN1.12 R52.1 U4.6 U4_1.6 | length 1896.7
  Top Layer w8: U4_1.6@-965.51,514.9 -965.51,480.8 -947.8,463.08 U4.6@-947.8,440.09
  Top Layer w10: CN1.12@-1100,-200 -1100,-75 -947.8,77.2 U4.6@-947.8,435.09 ; v4@-1049.59,-380.41 -950,-480 R52.1@-176,-480
  Bottom Layer w12: CN1.12@-1100,-200 -1050,-250 v4(-1050,-380.81)
MG_PB2: CN1.13 R49.1 U4.7 U4_1.7 | length 2253.9
  Top Layer w8: U4_1.7@-945.83,514.9 -945.83,490.11 -916.3,460.58 U4.7@-916.3,440.09
  Top Layer w10: CN1.13@-1000,-300 -1000,-340 -930,-410 v4(-230,-410) ; CN1.13@-1000,-280 -1050,-230 -1050,-65 -915.16,69.84 -915.16,440.09 U4.7@-915.16,454.97 ; v4(161.27,-314.73) R49.1@210,-314.73
  Top Layer w12: R49.1@210,-314.73 R49.1@215.27,-314.73
  Bottom Layer w12: v4(-230,-410) 120,-410 161.27,-368.73 v4(161.27,-314.73)
MG_PB3: CN1.14 R50.1 U4.8 U4_1.8 | length 2246.8
  Top Layer w8: U4_1.8@-926.14,514.9 -926.14,507.36 -884.8,466.02 U4.8@-884.8,440.09
  Top Layer w10: CN1.14@-1000,-220 CN1.14@-1000,-200 ; U4.8@-884.8,435.09 -884.8,60.2 -1000,-55 CN1.14@-1000,-200 ; v4(-250,-380) -920,-380 -950,-350 -950,-250 CN1.14@-1000,-200 ; v4(130,-355) 240,-355 280,-315 R50.1@280,-303
  Bottom Layer w12: v4(-250,-380) 105,-380 v4(130,-355)
MG_PB8(TX): CN1.33 D11.2 J5.2 J15.2 R51.1 U4.9 U4_1.9 | length 2446.5
  Top Layer w8: U4_1.9@-896.61,544.43 -888.2,544.43 -846.87,503.09 U4.9@-821.81,503.09
  Top Layer w10: U4.9@-817.87,502.02 -722.02,502.02 -649.75,429.75 -649.75,199.75 -580,130 -120,130 -100,110 R51.1@-100,50 ; R51.1@-100,43 R51.1@-100,50 ; CN1.33@100,100 50,50 R51.1@-100,50 ; J15.2@500,400 J5.2@700,400 760,340 760,165 D11.2@760,150
  Bottom Layer w12: CN1.33@100,100 285,100 440,255 440,345 495,400 J15.2@500,400
MG_PB9(RX): CN1.34 D12.1 J5.1 J15.1 R53.1 U4.10 U4_1.10 | length 2852.3
  Top Layer w8: U4_1.10@-896.61,564.11 -871.83,564.11 -842.3,534.58 U4.10@-821.81,534.58
  Top Layer w10: U4.10@-817.87,533.52 -718.52,533.52 -625,440 -625,210 -570,155 -100,155 -45,100 CN1.34@0,100 ; R53.1@218,-400 v4@237.56,-400 ; J15.1@500,300 J5.1@700,300 J5.1@705.77,294.23 ; J5.1@720,298 720,85 D12.1@773.39,31.61
  Bottom Layer w12: CN1.34@0,100 50,50 225.16,50 ; v4(237.56,-390) 237.56,37.6 ; J15.1@500,300 500,270 280,50 249.96,50 ; 225.16,50 237.56,37.6 ; 225.16,50 237.56,50 ; 237.56,37.6 237.56,50 ; 237.56,37.6 249.96,50 ; 237.56,50 249.96,50
MG_PB10: CN1.35 R47.1 SW3.1 U4.11 U4_1.11 | length 1664.8
  Top Layer w8: U4_1.11@-896.61,583.8 -862.51,583.8 -844.8,566.08 U4.11@-821.81,566.08
  Top Layer w10: U4.11@-817.87,565.02 -715.02,565.02 -560,410 SW3.1@-560,270 -470,180 -80,180 -50,150 50,150 CN1.35@100,200 ; CN1.35@110,190 160,140 160,-120 190,-150 R47.1@207,-150
MG_PB11: CN1.36 R46.1 SW4.1 U4.12 U4_1.12 | length 1601
  Top Layer w8: U4_1.12@-896.61,603.48 -850.2,603.48 -844.29,597.57 U4.12@-821.81,597.57
  Top Layer w10: U4.12@-817.87,596.51 -626.51,596.51 SW4.1@-561.4,531.4 ; SW4.1@-577.79,549.7 -560.45,532.35 -500,471.9 -500,250 -455,205 -5,205 CN1.36@0,200 ; SW4.1@-557.79,530 SW4.1@-557.79,535 ; CN1.36@10,210 30,210 ; CN1.36@20,200 30,210 ; R46.1@195,45 195,60 195,185 130,250 70,250 30,210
